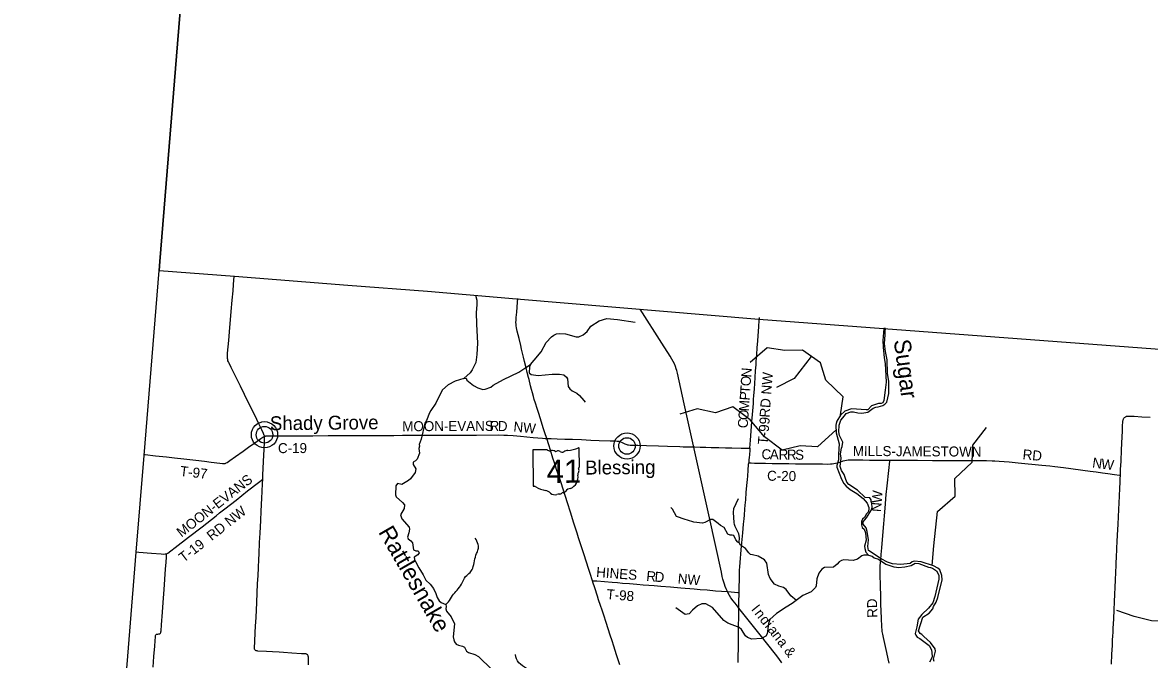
# Model space of a CAD drawing. Extents: x -51392 to 1635000, y 156707 to 696232.
# Drawn here: x 74563 to 108334, y 540953 to 560042 of the extents above; entities that cross this region are included whole.
import ezdxf

# ---------------------------------------------------------------- set-up
doc = ezdxf.new("R2010")
doc.units = 0
for name, color, linetype in [('GM_X_Adjacent_County', 7, 'Continuous'), ('GM_X_County', 7, 'Continuous'), ('GM_X_County_Road', 7, 'Continuous'), ('GM_X_County_Road_Text', 7, 'Continuous'), ('GM_X_Major_River', 7, 'Continuous'), ('GM_X_Major_River_Text', 7, 'Continuous'), ('GM_X_Minor_River', 7, 'Continuous'), ('GM_X_Minor_River_Text', 7, 'Continuous'), ('GM_X_Rail_Line', 7, 'Continuous'), ('GM_X_Rail_Line_Text', 7, 'Continuous'), ('GM_X_State_Route', 7, 'Continuous'), ('GM_X_State_Shield', 7, 'Continuous'), ('GM_X_Township', 7, 'Continuous'), ('GM_X_Township_Road', 7, 'Continuous'), ('GM_X_Township_Road_Text', 7, 'Continuous'), ('GM_X_Unincorporated', 7, 'Continuous'), ('GM_X_Unincorporated_Text', 7, 'Continuous')]:
    doc.layers.add(name, color=color, linetype=linetype)

msp = doc.modelspace()

# ---------------------------------------------------------------- linework, layer by layer
at = {"layer": 'GM_X_Adjacent_County'}
for points in [[(74563, 502065), (74862, 505867), (75172, 509582), (75227, 510268), (75674, 515788), (75743, 516628), (75955, 519254), (76337, 523966), (76597, 527182), (76801, 529705), (77124, 533695), (77266, 535451), (77972, 544170), (78206, 547064), (78655, 552615), (78677, 552881), (79341, 561012)], [(79341, 561012), (78677, 552881), (78655, 552615), (80912, 552436), (84311, 552167), (86696, 551986), (89363, 551763), (96623, 551154), (109974, 550151)]]:
    msp.add_lwpolyline(points, dxfattribs=at)
at = {"layer": 'GM_X_County'}
msp.add_lwpolyline([(74563, 502065), (74862, 505867), (75172, 509582), (75227, 510268), (75674, 515788), (75743, 516628), (75955, 519254), (76337, 523966), (76597, 527182), (76801, 529705), (77124, 533695), (77266, 535451), (77972, 544170), (78206, 547064), (78655, 552615), (80912, 552436), (84311, 552167), (86696, 551986), (89363, 551763), (96623, 551154), (109974, 550151)], dxfattribs=at)
at = {"layer": 'GM_X_County_Road'}
for points in [[(81813, 547641), (81812, 547651), (81808, 547666), (81798, 547697), (81786, 547728), (81738, 547831), (81638, 548038), (81529, 548258), (81339, 548640), (81094, 549141), (80913, 549508), (80818, 549699), (80752, 549831), (80731, 549876), (80719, 549907), (80710, 549939), (80705, 549972), (80702, 550005), (80703, 550054), (80709, 550136), (80743, 550512), (80765, 550773), (80817, 551378), (80847, 551721), (80871, 551998), (80888, 552194), (80909, 552438)], [(81760, 546361), (81765, 546472), (81785, 546881), (81803, 547257), (81816, 547469), (81818, 547551), (81818, 547589), (81815, 547621), (81813, 547641)], [(81813, 547641), (81840, 547650), (81856, 547653), (81871, 547655), (82018, 547657), (82346, 547658), (82608, 547659), (83018, 547658), (83264, 547659), (83722, 547661), (84001, 547662), (84526, 547665), (84968, 547668), (85329, 547668), (85689, 547670), (85951, 547671), (86230, 547672), (86378, 547673), (86509, 547673), (86656, 547674), (86836, 547674), (87099, 547674), (87541, 547677), (87721, 547677), (87853, 547678), (88164, 547679), (88836, 547682), (88983, 547680), (89098, 547674), (89261, 547661), (89489, 547641), (89864, 547606), (90142, 547582), (90224, 547575), (90270, 547572)], [(90270, 547572), (90400, 547575), (90580, 547567), (90810, 547559), (91039, 547551), (91318, 547541), (91597, 547530), (91843, 547519), (92171, 547509), (92335, 547504), (92384, 547500), (92433, 547493), (92464, 547486), (92511, 547469), (92555, 547448), (92614, 547419), (92644, 547405), (92675, 547394), (92691, 547390), (92723, 547384), (92772, 547380), (92870, 547377), (93001, 547372), (93264, 547365), (93625, 547354), (93887, 547344), (94264, 547332), (94362, 547330), (94510, 547327), (94707, 547322), (94871, 547317), (95035, 547312), (95199, 547307), (95363, 547303), (95428, 547302), (95625, 547297), (95822, 547292), (96100, 547288), (96248, 547285), (96360, 547281)], [(96360, 547281), (96359, 547234), (96357, 547201), (96348, 547101), (96347, 547084), (96338, 547001), (96332, 546934), (96331, 546901), (96330, 546884), (96327, 546846)], [(96327, 546846), (96367, 546843), (96401, 546841), (96498, 546837), (96629, 546835), (96728, 546833), (96826, 546831), (97023, 546829), (97203, 546826), (97531, 546822), (97728, 546820), (97958, 546817), (98188, 546816), (98302, 546815), (98434, 546813), (98532, 546812), (98696, 546809), (98778, 546811), (98827, 546814), (98876, 546821), (98924, 546831), (98987, 546849), (99081, 546880), (99158, 546906), (99206, 546919), (99254, 546928), (99303, 546933), (99369, 546935), (99484, 546935), (99648, 546934), (99746, 546933), (99943, 546930), (100189, 546928), (100435, 546927), (100560, 546927)], [(100560, 546927), (100632, 546927), (100812, 546926), (101059, 546924), (101387, 546922), (101830, 546918), (102076, 546916), (102191, 546916), (102371, 546914), (102584, 546914), (103191, 546912), (103454, 546912), (103618, 546910), (103700, 546908), (103831, 546898), (104125, 546871), (104403, 546844), (105105, 546777), (105350, 546751), (105496, 546734), (105757, 546701), (106554, 546595), (106733, 546572), (106928, 546545), (107091, 546524), (107286, 546497), (107432, 546480), (107463, 546476)], [(83137, 540789), (83130, 540986), (83129, 541019), (83126, 541051), (83123, 541066), (83117, 541081), (83108, 541093), (83097, 541103), (83084, 541110), (83069, 541114), (83054, 541117), (83021, 541119), (82923, 541124), (82628, 541145), (82383, 541161), (82252, 541170), (82055, 541182), (81875, 541193), (81613, 541206), (81596, 541207), (81579, 541209), (81563, 541214), (81547, 541222), (81534, 541233), (81525, 541247), (81518, 541263), (81516, 541280), (81515, 541297), (81524, 541495), (81537, 541757), (81547, 541953), (81560, 542215), (81581, 542658), (81608, 543231), (81620, 543461), (81631, 543706), (81642, 543952), (81650, 544116), (81667, 544460), (81681, 544739), (81700, 545115), (81714, 545394), (81733, 545787), (81742, 545984), (81753, 546230), (81760, 546361)]]:
    msp.add_lwpolyline(points, dxfattribs=at)
at = {"layer": 'GM_X_Major_River'}
for points in [[(88137, 551867), (88176, 551718), (88181, 551577), (88156, 551355), (88165, 551002), (88198, 550434), (88179, 550093), (88144, 549849), (88037, 549632), (87972, 549541), (87788, 549374), (87529, 549289), (87320, 549180), (87150, 549029), (87045, 548848), (86948, 548633), (86801, 548414), (86759, 548344), (86664, 548119)], [(86664, 548119), (86616, 548030), (86510, 547551), (86446, 547399), (86454, 547344), (86438, 547274), (86454, 547140), (86390, 546954), (86340, 546902), (86270, 546866), (86268, 546795), (86352, 546667), (86332, 546553), (86188, 546369), (86126, 546318), (85927, 546194), (85803, 546228), (85753, 546156), (85735, 545884), (85763, 545826), (85947, 545659), (86009, 545589), (85995, 545481), (85891, 545290), (85925, 545170), (86146, 544913), (86162, 544859), (86134, 544745), (86102, 544621), (86122, 544570), (86198, 544508), (86244, 544446), (86278, 544240), (86348, 544211), (86422, 544209), (86452, 544147), (86408, 544089), (86302, 544015), (86306, 543951), (86336, 543885), (86434, 543696), (86570, 543485), (86649, 543332)], [(86649, 543332), (86775, 543213), (86875, 543077), (86948, 542931), (86984, 542811), (87045, 542711), (87111, 542657), (87247, 542598), (87259, 542543), (87250, 542473), (87268, 542405), (87410, 542229), (87509, 542025), (87467, 541626), (87483, 541540), (87507, 541476), (87558, 541408), (87624, 541377), (87752, 541351), (87806, 541317), (87868, 541201), (87923, 541165), (88117, 541102), (88223, 541043), (88628, 540656)]]:
    msp.add_lwpolyline(points, dxfattribs=at)
at = {"layer": 'GM_X_Minor_River'}
for p in [(100424, 550870), (100373, 550874)]:
    msp.add_line(p, (100373, 550874), dxfattribs=at)
for points in [[(87788, 549374), (87854, 549383), (87877, 549323), (88077, 549163), (88209, 549094), (88355, 549046), (88425, 549051), (88593, 549110), (88667, 549178), (88972, 549346), (89439, 549564), (89650, 549703), (89780, 549794), (89899, 549919), (90102, 550176), (90254, 550449), (90412, 550618), (90485, 550674), (90567, 550709), (90657, 550721), (90837, 550710), (91153, 550625), (91233, 550624), (91359, 550682), (91484, 550785), (91588, 550940), (91843, 551099), (92072, 551170), (92388, 551138), (92924, 551064)], [(100373, 550874), (100346, 550516), (100351, 550310), (100388, 549991), (100413, 549819), (100441, 549262), (100414, 549022), (100374, 548713), (100342, 548647), (100292, 548629), (100218, 548628), (100007, 548559), (99889, 548439), (99839, 548432), (99401, 548465), (99204, 548392), (99072, 548277), (98961, 548090), (98943, 548028), (98932, 547978), (98949, 547747), (99032, 547419), (99011, 547105), (99018, 546934), (98969, 546762), (98969, 546712), (99104, 546358), (99175, 546230), (99245, 546150), (99366, 546046), (99564, 545925), (99758, 545775), (99875, 545636), (99921, 545504), (99928, 545440), (99906, 545369), (99856, 545317), (99799, 545209), (99739, 545154), (99707, 545090), (99700, 544984), (99726, 544906), (99782, 544854), (99827, 544746), (99844, 544529), (99798, 544349), (99809, 544279), (99837, 544165), (99917, 544081), (100027, 544051), (100088, 543996), (100210, 543954), (100438, 543809), (100674, 543728), (100748, 543720), (100810, 543708), (101000, 543729), (101192, 543772), (101308, 543839), (101418, 543831), (101712, 543720), (101774, 543706), (101834, 543691), (101948, 543605), (102017, 543481), (102025, 543363), (101903, 542841), (101846, 542649), (101715, 542486), (101512, 542301), (101402, 542162), (101361, 541929), (101316, 541727), (101331, 541677), (101375, 541623), (101455, 541581), (101730, 541372), (101800, 541244), (101821, 541052), (101813, 540997), (101746, 540871)], [(100391, 550424), (100414, 550687), (100418, 550786), (100424, 550870)], [(99078, 548282), (99158, 548824), (98636, 549325), (98476, 549847), (97933, 550219), (97407, 550211), (96879, 550294), (96363, 549855)], [(100527, 549295), (100486, 549527), (100469, 549928), (100424, 550180), (100391, 550424)], [(89780, 549794), (89754, 549726), (89749, 549547), (89807, 549494), (90019, 549461), (90436, 549502), (90656, 549503), (90784, 549484)], [(98193, 550035), (97689, 549369), (97160, 549108)], [(90784, 549484), (90868, 549416), (90889, 549366), (90918, 549138), (90964, 549064), (91034, 549006), (91176, 548935), (91255, 548865), (91379, 548712), (91426, 548667)], [(101881, 540894), (101863, 540958), (101920, 541198), (101910, 541268), (101775, 541462), (101575, 541640), (101510, 541701), (101458, 541731), (101412, 541807), (101542, 542225), (101728, 542344), (101839, 542468), (101861, 542539), (101944, 542673), (101991, 542806), (102123, 543343), (102111, 543467), (102048, 543637), (101992, 543691), (101860, 543761), (101495, 543878), (101283, 543901), (101221, 543876), (101160, 543832), (100884, 543797), (100634, 543816), (100488, 543867), (100294, 543972), (99915, 544215), (99896, 544335), (99911, 544536), (99874, 544792), (99846, 544900), (99750, 545006), (99755, 545078), (99853, 545193), (100002, 545438), (100025, 545510), (100017, 545626), (99997, 545684), (99998, 545736), (99958, 545792), (99818, 545802), (99583, 546031), (99323, 546192), (99261, 546264), (99220, 546372), (99182, 546494), (99101, 546616), (99061, 546734), (99094, 546985), (99075, 547115), (99104, 547287), (99120, 547339), (99140, 547462), (99045, 547666), (99023, 547770), (99034, 547972), (99083, 548129), (99194, 548251), (99246, 548324), (99386, 548376), (99464, 548379), (99598, 548341), (99714, 548332), (99896, 548367), (100053, 548485), (100131, 548516), (100201, 548524), (100348, 548563), (100406, 548601), (100466, 548669), (100525, 548920), (100527, 549295)], [(98943, 547830), (98389, 547328), (97863, 547358), (97324, 547223), (96802, 547630), (96371, 548139), (95847, 548521), (95324, 548342), (94778, 548460), (94261, 548306)], [(101825, 543770), (101869, 544354), (101981, 545386), (102507, 545848), (102502, 546374), (103018, 546862), (103036, 547374), (103451, 547903)], [(97753, 542721), (97590, 542856), (97445, 543054), (97367, 543110), (97223, 543145), (97097, 543205), (96966, 543377), (96922, 543499), (96868, 543835), (96802, 543939), (96605, 544044), (96435, 544090), (96381, 544103), (96327, 544147), (96225, 544277), (96080, 544383), (96038, 544449), (96047, 544607), (96031, 544721), (95918, 544933), (95900, 545001), (95892, 545057), (95866, 545356), (95878, 545482), (96019, 545781)], [(96037, 544453), (96000, 544473), (95942, 544536), (95879, 544666), (95827, 544682), (95773, 544676), (95703, 544710), (95592, 544912), (95478, 544969), (95412, 545031), (95246, 545144), (95176, 545146), (95012, 545057), (94944, 545039), (94678, 545068), (94492, 545127), (94420, 545149), (94162, 545238), (94043, 545462), (93987, 545510)], [(99917, 544081), (99773, 544080), (99712, 544054), (99584, 543957), (99454, 543917), (99174, 543939), (99103, 543923), (99033, 543879), (98975, 543812), (98870, 543720), (98596, 543704), (98518, 543660), (98423, 543535), (98369, 543369), (98344, 543164), (98328, 543108), (98199, 542981), (97946, 542868), (97629, 542626), (97449, 542515), (97156, 542331), (96961, 542152), (96920, 542026), (96873, 541717), (96839, 541649), (96710, 541578), (96422, 541565)], [(114157, 542576), (113635, 542717), (113109, 542819), (112580, 542556), (112059, 542580), (111035, 542665), (110517, 542799), (109971, 542799), (109445, 542464), (108920, 542099), (108393, 542109), (107876, 542237), (107354, 542419)], [(96422, 541565), (96286, 541610), (96226, 541658), (96113, 541848), (96043, 541912), (95700, 542042), (95582, 542122), (95237, 542507), (95044, 542619), (94920, 542618), (94787, 542561), (94643, 542434), (94544, 542322), (94422, 542297), (94137, 542504)]]:
    msp.add_lwpolyline(points, dxfattribs=at)
for points in [[(87247, 542598), (87323, 542676), (87446, 542865), (87716, 543207), (87841, 543442), (87973, 543555), (88052, 543685), (88168, 544129), (88220, 544257), (88215, 544396), (88128, 544592)], [(89015, 539960), (89086, 540038), (89156, 540223), (89219, 540273), (89293, 540294), (89451, 540260), (89643, 540251), (89711, 540290), (89751, 540360), (89759, 540410), (89714, 540618), (89661, 540680), (89431, 540856), (89332, 541100)]]:
    msp.add_spline(points, degree=3, dxfattribs=at)
at = {"layer": 'GM_X_Rail_Line'}
msp.add_lwpolyline([(97319, 540849), (97225, 540981), (97124, 541113), (96665, 541691), (96029, 542490), (95954, 542585), (95854, 542714), (95792, 542802), (95750, 542870), (95712, 542938), (95676, 543011), (95647, 543074), (95620, 543143), (95596, 543210), (95577, 543271), (95553, 543355), (95532, 543443), (95504, 543569), (95145, 545199), (95027, 545736), (94392, 548617), (94189, 549533), (94170, 549609), (94152, 549667), (94126, 549738), (94098, 549808), (94062, 549878), (94019, 549955), (93968, 550039), (93719, 550429), (93068, 551451)], dxfattribs=at)
at = {"layer": 'GM_X_State_Route'}
for points in [[(92463, 540794), (92366, 541091), (92280, 541356), (92229, 541512), (92172, 541683), (92049, 542057), (91978, 542276), (91928, 542432), (91882, 542572), (91826, 542744), (91790, 542853), (91709, 543102), (91654, 543274), (91643, 543307), (91573, 543524), (91512, 543711), (91471, 543836), (91370, 544148), (91275, 544445), (91226, 544601), (91181, 544742), (91077, 545070), (91022, 545242), (90981, 545367), (90889, 545648), (90700, 546242), (90650, 546398), (90614, 546507), (90568, 546647), (90532, 546756), (90502, 546849), (90457, 546990), (90382, 547224), (90331, 547381), (90270, 547572), (90216, 547740), (90167, 547896), (90083, 548162), (90023, 548350), (89983, 548475), (89933, 548631), (89899, 548741), (89871, 548835), (89841, 548946), (89817, 549042), (89789, 549153), (89741, 549344), (89726, 549408), (89690, 549551), (89655, 549694), (89608, 549886), (89577, 550013), (89519, 550252), (89493, 550364), (89441, 550571), (89387, 550794), (89367, 550891), (89356, 550956), (89352, 551005), (89350, 551054), (89352, 551120), (89357, 551202), (89372, 551366), (89399, 551660), (89410, 551770)], [(107196, 540815), (107210, 541110), (107224, 541372), (107230, 541520), (107239, 541667), (107244, 541749), (107250, 541880), (107263, 542175), (107276, 542437), (107286, 542682), (107295, 542912), (107304, 543108), (107314, 543338), (107335, 543780), (107350, 544091), (107355, 544189), (107359, 544288), (107368, 544484), (107377, 544681), (107392, 545008), (107413, 545451), (107434, 545844), (107446, 546089), (107454, 546253), (107458, 546368), (107463, 546476), (107463, 546483), (107470, 546646), (107482, 546892), (107497, 547236), (107514, 547629), (107521, 547793), (107528, 547957), (107535, 548072), (107539, 548105), (107542, 548121), (107546, 548137), (107552, 548153), (107558, 548169), (107567, 548183), (107577, 548197), (107589, 548209), (107603, 548219), (107617, 548228), (107633, 548235), (107649, 548240), (107665, 548244), (107698, 548247), (107748, 548246), (107879, 548240), (108109, 548227), (108354, 548216)]]:
    msp.add_lwpolyline(points, dxfattribs=at)
at = {"layer": 'GM_X_State_Shield'}
for p, q in [((89853, 547218), (89863, 546162)), ((90275, 547240), (89867, 547236)), ((91250, 546723), (91245, 547276)), ((91250, 546723), (91250, 546723))]:
    msp.add_line(p, q, dxfattribs=at)
for centre, radius, start, end in [((89869, 547221), 16.1, 98.6686, 188.6686), ((90371, 547364), 156, 232.1581, 271.6504), ((90429, 546649), 562, 81.0252, 95.5268), ((90551, 547232), 45.1, 220.3306, 297.6409), ((90619, 547111), 93.8, 55.0052, 119.6797), ((90738, 547280), 113, 234.3948, 295.3667), ((90941, 546924), 297, 97.8847, 121.3074), ((90736, 548685), 1476, 276.383, 289.445), ((91230, 547278), 15.5, 352.4006, 98.2765), ((90840, 546417), 369, 292.8474, 9.5244), ((91308, 546492), 105, 137.345, 187.4681), ((91247, 546682), 24, 108.4825, 210.8755), ((91095, 546611), 144, 340.5715, 24.1881), ((91234, 546721), 16.6, 290.1424, 8.2727), ((89879, 546159), 16.3, 172.4969, 258.8452), ((89881, 546268), 124, 267.8775, 281.1424), ((89908, 546101), 44.8, 30.2869, 93.8103), ((90464, 547056), 1066, 240.9515, 257.737), ((91001, 545876), 202, 94.9417, 143.1153), ((90159, 545690), 334, 47.7227, 76.3745), ((90516, 546102), 212, 231.2389, 286.8304), ((90642, 545737), 174, 86.2337, 111.7485), ((90655, 546024), 113, 269.3156, 316.0878), ((90758, 545922), 31.8, 66.2903, 133.187), ((90743, 546067), 119, 283.4117, 323.8157)]:
    msp.add_arc(centre, radius, start, end, dxfattribs=at)
at = {"layer": 'GM_X_Township'}
msp.add_lwpolyline([(77266, 535451), (77972, 544170), (78206, 547064), (78655, 552615), (80912, 552436), (84311, 552167), (86696, 551986), (89363, 551763), (96623, 551154), (109974, 550151)], dxfattribs=at)
at = {"layer": 'GM_X_Township_Road'}
for points in [[(96360, 547281), (96381, 547529), (96399, 547791), (96420, 548085), (96436, 548297), (96453, 548510), (96463, 548624), (96472, 548755), (96479, 548853), (96494, 549065), (96506, 549228), (96517, 549408), (96530, 549604), (96543, 549784), (96549, 549882), (96565, 550095), (96579, 550291), (96594, 550503), (96627, 550928), (96641, 551108), (96646, 551201)], [(78213, 547096), (78236, 547093), (78547, 547059), (78873, 547024), (79118, 546998), (79396, 546967), (79755, 546924), (80016, 546892), (80211, 546869), (80472, 546834), (80553, 546823), (80570, 546821), (80586, 546821), (80603, 546822), (80619, 546825), (80635, 546829), (80650, 546835), (80664, 546842), (80693, 546859), (80773, 546916), (80948, 547039), (81177, 547199), (81338, 547312), (81525, 547446), (81699, 547571), (81764, 547615), (81783, 547627), (81813, 547641)], [(96034, 542961), (96035, 543043), (96038, 543158), (96044, 543305), (96047, 543469), (96048, 543535), (96052, 543633), (96059, 543731), (96070, 543861), (96102, 544237), (96119, 544450), (96145, 544744), (96169, 545005), (96184, 545168), (96194, 545282), (96210, 545462), (96221, 545576), (96234, 545740), (96252, 545952), (96270, 546165), (96285, 546344), (96293, 546442), (96308, 546622), (96322, 546795), (96327, 546846)], [(100537, 540844), (100507, 540972), (100465, 541164), (100425, 541340), (100363, 541612), (100342, 541708), (100327, 541789), (100321, 541838), (100314, 541919), (100302, 542198), (100296, 542395), (100288, 542624), (100283, 542805), (100270, 543198), (100262, 543460), (100260, 543575), (100261, 543657), (100266, 543755), (100280, 543935), (100294, 544099), (100310, 544295), (100350, 544785), (100369, 545014), (100391, 545259), (100410, 545488), (100445, 545897), (100471, 546158), (100524, 546614), (100556, 546891), (100560, 546927)], [(78878, 544122), (78882, 544123), (78898, 544130), (78912, 544139), (79005, 544206), (79136, 544306), (79541, 544613), (79942, 544927), (80367, 545262), (80470, 545343), (80625, 545465), (80960, 545728), (81308, 546003), (81631, 546256), (81760, 546361)], [(77975, 544174), (78046, 544169), (78423, 544142), (78717, 544119), (78799, 544113), (78833, 544114), (78849, 544115), (78866, 544118), (78878, 544122)], [(78477, 540726), (78501, 541037), (78526, 541348), (78537, 541512), (78543, 541627), (78547, 541660), (78551, 541675), (78558, 541690), (78568, 541701), (78581, 541710), (78597, 541714), (78614, 541715), (78647, 541716), (78663, 541718), (78678, 541723), (78691, 541732), (78701, 541745), (78707, 541760), (78711, 541776), (78715, 541809), (78728, 541989), (78753, 542366), (78776, 542660), (78805, 543053), (78849, 543659), (78866, 543872), (78877, 544019), (78880, 544077), (78879, 544103), (78878, 544122)], [(91643, 543307), (91675, 543307), (91707, 543308), (91773, 543305), (92002, 543287), (92231, 543268), (92395, 543256), (92542, 543244), (92755, 543227), (92968, 543210), (93164, 543194), (93328, 543181), (93491, 543166), (93688, 543150), (93982, 543125), (94293, 543100), (94686, 543067), (94866, 543053), (95079, 543035), (95324, 543014), (95684, 542986), (95799, 542976), (95897, 542969), (95995, 542964), (96034, 542961)], [(96006, 540863), (96012, 541093), (96016, 541240), (96018, 541355), (96019, 541437), (96019, 541519), (96020, 541682), (96021, 541830), (96022, 541994), (96025, 542191), (96027, 542289), (96029, 542453), (96032, 542699), (96034, 542912), (96034, 542961)]]:
    msp.add_lwpolyline(points, dxfattribs=at)
at = {"layer": 'GM_X_Unincorporated'}
for centre, radius in [((81814, 547687), 393), ((81814, 547687), 249), ((92677, 547351), 393), ((92677, 547351), 249)]:
    msp.add_circle(centre, radius, dxfattribs=at)

# ---------------------------------------------------------------- texts
at = {"layer": 'GM_X_County_Road_Text'}
for s, rotation, p in [('MOON-EVANS', 0.2322, (85943, 547793)), ('R', 359.3364, (88557, 547804)), ('D', 358.4362, (88803, 547801)), ('NW', 354.7891, (89265, 547783)), ('C-19', 0.1943, (82218, 547136)), ('C', 357.9851, (96702, 546958)), ('A', 359.3074, (96956, 546950)), ('R', 359.3051, (97220, 546946)), ('R', 359.3089, (97467, 546943)), ('S', 359.3031, (97713, 546940)), ('MILLS-JAMESTOWN', 359.6714, (99442, 547053)), ('RD', 354.6318, (104522, 546955)), ('N', 351.9901, (106607, 546709)), ('W', 352.8652, (106873, 546672)), ('C-20', 359.1762, (96873, 546310))]:
    msp.add_text(s, height=300, rotation=rotation, dxfattribs=at).set_placement(p)
at = {"layer": 'GM_X_Major_River_Text'}
msp.add_text('Rattlesnake', height=500.2, rotation=299.9802, dxfattribs=at).set_placement((85212, 544773))
at = {"layer": 'GM_X_Minor_River_Text'}
msp.add_text('Sugar', height=500, rotation=277.4827, dxfattribs=at).set_placement((100670, 550518))
at = {"layer": 'GM_X_Rail_Line_Text'}
for s, rotation, p in [('I', 308.4907, (96385, 542452)), ('n', 308.4888, (96486, 542325)), ('d', 308.4888, (96639, 542132)), ('i', 308.4882, (96793, 541939)), ('a', 308.4929, (96878, 541832)), ('n', 308.4248, (97012, 541664)), ('a', 307.8991, (97164, 541471)), ('&', 305.7781, (97368, 541206))]:
    msp.add_text(s, height=299, rotation=rotation, dxfattribs=at).set_placement(p)
at = {"layer": 'GM_X_State_Shield'}
msp.add_text('41', height=696.1, rotation=0.5385, dxfattribs=at).set_placement((90270, 546240))
at = {"layer": 'GM_X_Township_Road_Text'}
for s, rotation, p in [('N', 85.6, (96397, 549397)), ('RD NW', 85.792, (96947, 548194)), ('T', 86.0511, (96364, 548910)), ('O', 86.0423, (96379, 549134)), ('P', 86.0545, (96350, 548708)), ('M', 86.0503, (96327, 548383)), ('C', 86.0533, (96292, 547874)), ('O', 86.0496, (96309, 548120)), ('T-99', 85.5984, (96894, 547386)), ('T-97', 353.2894, (79267, 546457)), ('MOON-EVANS', 38.0767, (79327, 544600)), ('W', 85.0493, (100306, 545627)), ('RD NW', 38.4495, (80232, 544495)), ('N', 85.4246, (100285, 545365)), ('T-19', 37.2671, (79391, 543847)), ('HINES', 355.6982, (91745, 543425)), ('R', 354.6074, (93245, 543310)), ('D', 355.5188, (93495, 543287)), ('NW', 355.1991, (94188, 543231)), ('T-98', 355.2504, (92053, 542765)), ('RD', 91.5132, (100182, 542204))]:
    msp.add_text(s, height=300, rotation=rotation, dxfattribs=at).set_placement(p)
at = {"layer": 'GM_X_Unincorporated_Text'}
for s, p in [('Shady Grove', (81978, 547822)), ('Blessing', (91424, 546494))]:
    msp.add_text(s, height=417, rotation=0.5386, dxfattribs=at).set_placement(p)

doc.saveas('drawing.dxf')
